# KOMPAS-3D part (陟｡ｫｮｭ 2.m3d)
File: created 29.01.2016 13:47:21, last saved 25.07.2016 11:16:17.
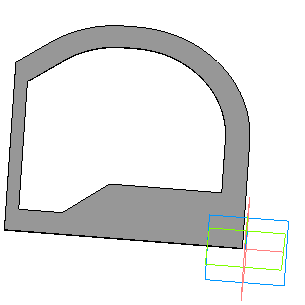
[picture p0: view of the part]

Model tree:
1. Эскиз:1
2. Операция выдавливания:1
     Толщина стенки 2 = 18; Расстояние 1 = 0.6
3. Эскиз:2
4. Вырезать элемент выдавливания:1
     Толщина стенки 2 = 2; Расстояние 1 = 30
5. Эскиз:3
6. Операция выдавливания:2
     Расстояние 1 = 0.6
7. Эскиз:4
8. Операция выдавливания:3
     Расстояние 1 = 0.6
9. Эскиз:5
10. Вырезать элемент выдавливания:2
     Расстояние 1 = 10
